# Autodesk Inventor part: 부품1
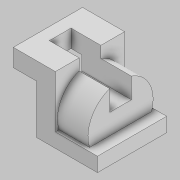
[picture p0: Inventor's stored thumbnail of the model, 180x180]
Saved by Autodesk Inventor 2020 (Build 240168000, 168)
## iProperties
Created: 2019-07
Part Number: 부품1
Material: 일반
Document SubType Name: Modeling
Designer: jys1b
Density: 1 g/cm^3
Appearance: 기본값
Author: jys1b
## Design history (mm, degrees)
sketch "스케치1"
  geometry: L1 (0, 0)-(0, 21); L2 (0, 21)-(62, 21); L3 (62, 21)-(62, 98); L4 (62, 98)-(124, 98); L5 (124, 98)-(124, 72); L6 (124, 72)-(90, 72); L7 (90, 72)-(90, 0); L8 (90, 0)-(0, 0)
  constraints: 16 end point, 7 perpendicular, 1 vertical
  dimensions: "d0" = 21 distance of L1.start L1.end; "d1" = 124 horizontal distance of L1.start L5.end; "d2" = 34 distance of L5.end L6.end; "d3" = 72 vertical distance of L5.end L7.end; "d4" = 98 distance between parallel lines of L8 L4; "d15" = 62 distance of L3.end L4.end
extrude "돌출1" new body sketch "스케치1" stored distance "d5" = 102; taper "d6" = 0 deg
sketch "스케치2"
  geometry: L1 (0, 0)-(0, 102) reference; L2 (21, 0)-(21, 102) reference; C1 r 48 at (-15, 51); 5 further points
  constraints: 2 horizontal alignment, 2 midpoint, 1 centre point
  dimensions: "d7" = 96 diameter of C1; "d8" = 15 distance from line of L1 C1.centre
extrude "돌출2" join sketch "스케치2" distance "d9" = 45; taper "d10" = 0 deg
sketch "스케치3"
  geometry: L1 (18, -35)-(196.719, -35); L2 (196.719, -35)-(196.719, -67); L3 (196.719, -67)-(18, -67); L4 (18, -67)-(18, -35); L5 (0, -102)-(0, 0) reference; 2 further points
  constraints: 8 end point, 2 parallel, 1 horizontal, 1 horizontal alignment, 1 midpoint, 1 perpendicular
  dimensions: "d11" = 32 distance of L1.end L2.end; "d12" = 18 distance between parallel lines of L4 L5
extrude "돌출3" cut sketch "스케치3" distance "d13" = 47; taper "d14" = 0 deg
node "솔리드1"
